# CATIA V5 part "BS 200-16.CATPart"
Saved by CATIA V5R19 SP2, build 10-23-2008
Part number: BS 200-16
Bounding box of the stored display mesh (mm): x -12.497 to 12.497, y -12.358 to 12.358, z 0 to 62
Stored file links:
  C:\Users\Bora\Desktop\3D Katı model\BS serisi\BS 200\BS 200-16.CATPart
  C:\Program Files\Dassault Systemes\B19\intel_a\reffiles\standard\MetricThickPitch.txt
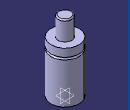
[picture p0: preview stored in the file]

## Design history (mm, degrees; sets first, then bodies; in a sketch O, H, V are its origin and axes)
Body1 (main body)
  Sketch1 on yz-plane, origin (0, 0, 0), H (0, 1, 0), V (0, 0, 1)
    point P1 (6, 61)
    point P3 (6, 61)
    point P5 (12.5, 38)
    point P6 (12.5, 36)
    point P8 (12.5, 36)
    point P9 (12.5, 38)
    line L1 (6, 61) -> (6, 45)
    arc A1 centre (5, 61) radius 1 from (6, 61) to (5, 62) ccw
    arc A2 centre (12.5, 37) radius 1 from (12.5, 38) to (12.5, 36) ccw
    line L2 (12.5, 0) -> (12.5, 36)
    line L3 (12.5, 38) -> (12.5, 45)
    line L4 (5, 62) -> (0, 62)
    point P11 (0, 62)
    line L5 (6, 45) -> (12.5, 45)
    line L6 (0, 0) -> (12.5, 0)
    coincidence: P11 V, P1 P3, P5 P9, P6 P8
    tangency: L4 A1
    horizontal: L5 H, L6 H
  Shaft1: profile Sketch1, axis Sketch1.V, angle 360
  Sketch2 on face of Shaft1 from Sketch1.L6, origin (0, 0, 0), H (1, 0, 0), V (0, -1, 0)
    point P1 (0, 0)
  Hole1: placed by Sketch2, at (0, 0, 0) direction (0, 0, 1), diameter 4.917, depth 4, threaded "M6", thread diameter 6, thread depth 4, pitch 1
